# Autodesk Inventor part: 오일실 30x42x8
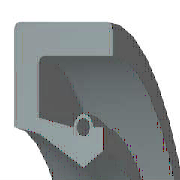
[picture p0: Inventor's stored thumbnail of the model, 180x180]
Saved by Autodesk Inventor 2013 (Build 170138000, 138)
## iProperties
IsCustomPart: 0
Created: 2009-02
Part Number: 오일실 30x42x8
Material: 고무
Document SubType Name: Modeling
Standard: KS B 2804
Designer: mdu
Standards Organization: KS
Language: ko-KR
Size Designation: S - 30 42 8
Categories: <MemberInstance><Categories><Category DisplayName="샤프트 부품" InternalName="7f7aeb1f-a693-4053-b835-cee3144e0d98" Mnemonic="SHFT"><Category DisplayName="실링" Intern
Density: 0.93 g/cm^3
Author: mdu
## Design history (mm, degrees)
revolve "본체" stored, may be unused: angle "d17" = 90 deg
revolve "스프링1" stored, may be unused: angle "d18" = 90 deg
body "Solid1"
sketch "스케치1"
  geometry: L1 (0, 21)-(8, 21); L2 (8, 21)-(8, 19.75); L3 (8, 19.75)-(1.75, 19.75); L4 (0, 21)-(0, 17.1); L5 (0, 17.1)-(1.75, 16.75); L6 (1.75, 16.75)-(4.9, 15); L7 (4.9, 15)-(0, 15); L8 (6.3, 15.875)-(6.3, 17.1); L9 (0, 0)-(9.586, 0) reference; L10 (4.9, 15)-(6.3, 15.875); L11 (0, 18)-(0, -3) reference; L12 (-1.917, 0)-(11.503, 0) reference; L13 (4.2, 17.1)-(1.75, 17.59); L14 (1.75, 17.59)-(1.75, 19.75); L15 (6.3, 17.1)-(5.6, 17.1); C1 r 0.455 at (4.9, 17.1); A1 r 0.7 centre (4.9, 17.1) between (5.6, 17.1) and (4.2, 17.1)
  constraints: 26 end point, 5 horizontal alignment, 4 perpendicular, 2 centre point, 2 collinear, 2 horizontal, 2 parallel, 2 point on circle, 2 point on line, 2 vertical alignment, 1 coincident
  dimensions: "d0" = 42 diameter of L1 L9 (= SD2); "d1" = 31.75 diameter of L8.start L9 (= ABDM); "d2" = 1.25 distance of L1.end L2.end (computed from SD); "d3" = 0.91 diameter of C1 (= SPDI); "d4" = 1.4 diameter of A1 (= SPDA); "d5" = 30 diameter of L6.end L9 (= NND); "d6" = 33.5 diameter of L5.end L9 (= TKDM); "d7" = 34.2 diameter of L4.end L9 (= HLDM); "d8" = 4.9 distance from line of C1.centre L4 (= SPDST); "d9" = 6.3 distance between parallel lines of L8 L4 (= SDI); "d10" = 8 distance between parallel lines of L2 L4 (= SWDT); "d12" = 1.75 distance between parallel lines of L14 L4 (= SD)
fillet "모깎기1" dims "d11" = 0.4 (= RR)
other parameters: "SD2" = 42 [user parameter; used in 1 equation term], "SWDT" = 8 [user parameter; used in 1 equation term], "RR" = 0.4 [user parameter; used in 1 equation term], "SD" = 1.75 [user parameter; used in 2 equation terms], "NND" = 30 [user parameter; used in 1 equation term], "SPDA" = 1.4 [user parameter; used in 1 equation term], "SPDI" = 0.91 [user parameter; used in 1 equation term], "TKDM" = 33.5 [user parameter; used in 1 equation term], "HLDM" = 34.2 [user parameter; used in 1 equation term], "ABDM" = 31.75 [user parameter; used in 1 equation term], "SDI" = 6.3 [user parameter; used in 1 equation term], "SPDST" = 4.9 [user parameter; used in 1 equation term], "d13" = 0, "d14" = 0, "d15" = 0, "LAB" = 0.35 [user parameter]
